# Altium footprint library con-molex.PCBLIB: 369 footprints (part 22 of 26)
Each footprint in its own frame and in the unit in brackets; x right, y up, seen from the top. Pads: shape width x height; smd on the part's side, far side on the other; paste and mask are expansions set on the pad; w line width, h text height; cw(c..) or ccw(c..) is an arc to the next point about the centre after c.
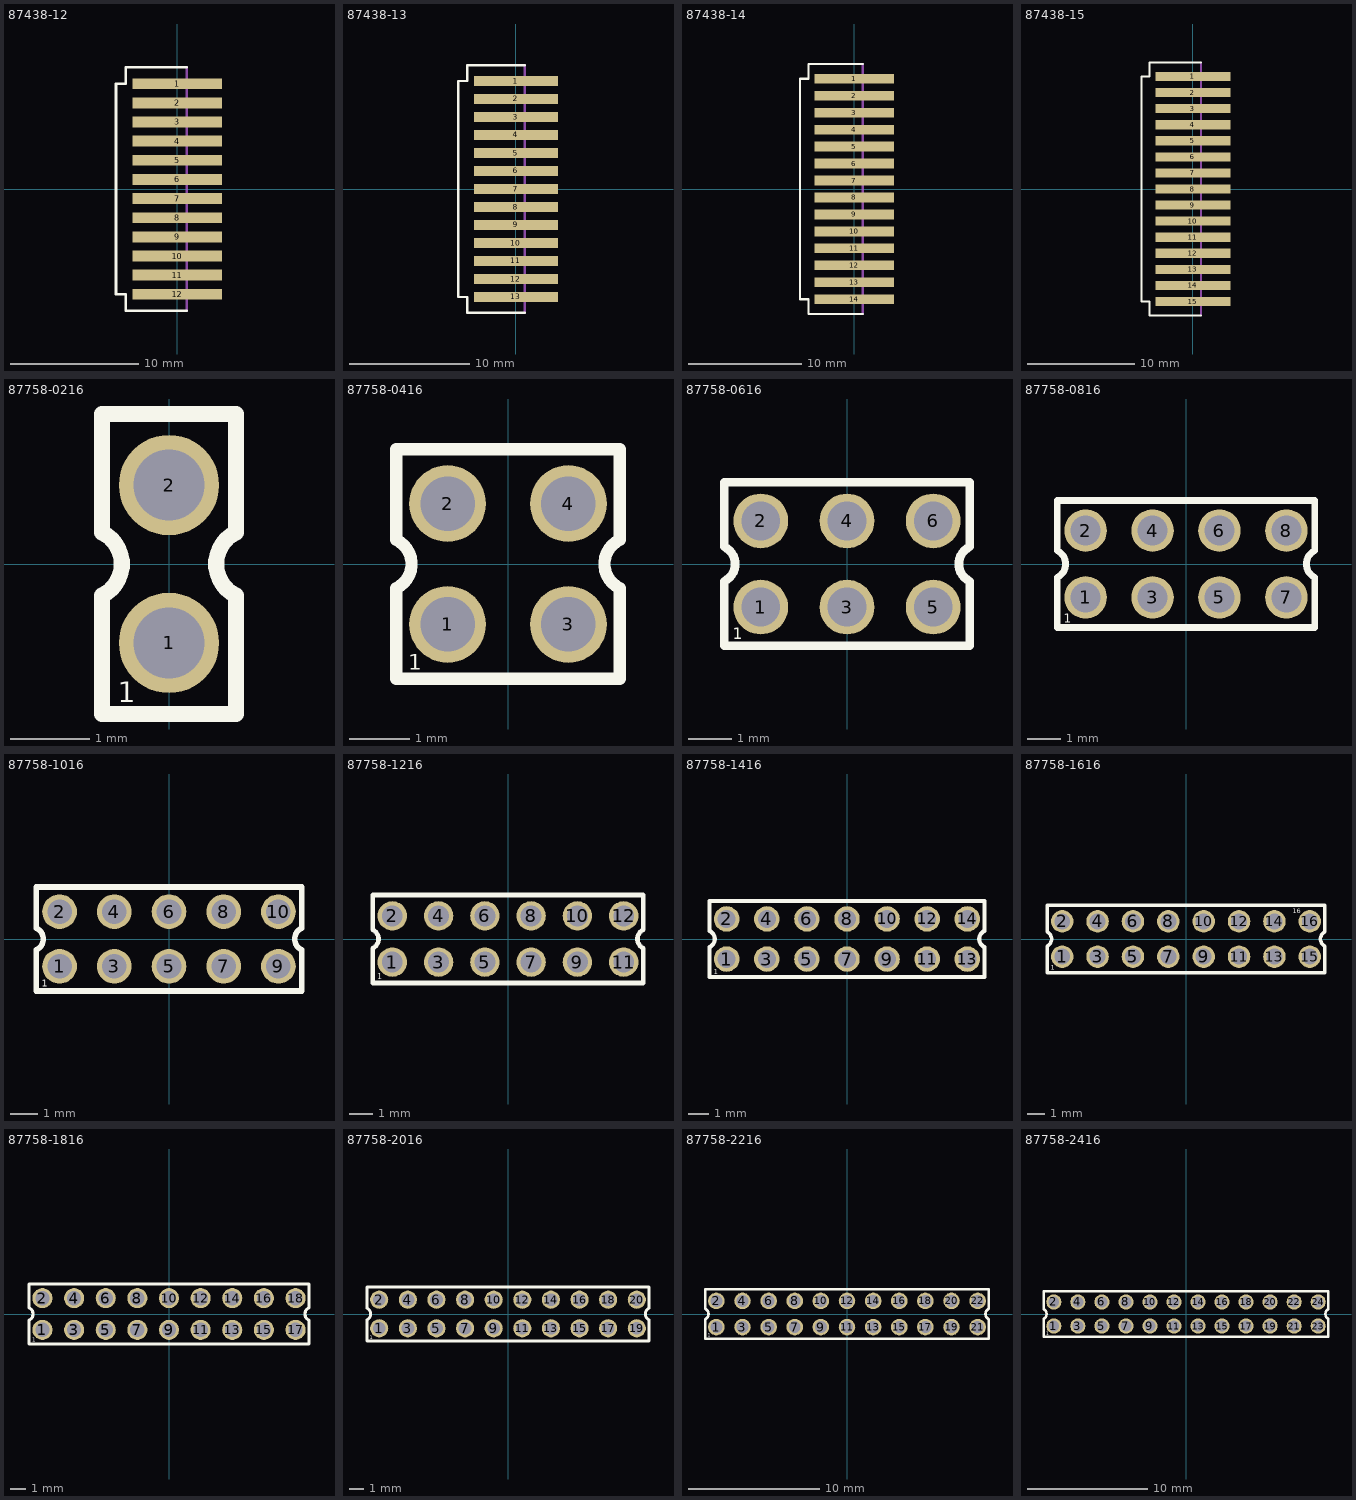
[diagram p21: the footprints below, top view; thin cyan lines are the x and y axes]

## 87438-12 [mm]
pads (12):
  rect 7x0.85 smd: 1(0,8.25) 2(0,6.75) 3(0,5.25) 4(0,3.75) 5(0,2.25) 6(0,0.75) 7(0,-0.75) 8(0,-2.25) 9(0,-3.75) 10(0,-5.25) 11(0,-6.75) 12(0,-8.25)
Top Overlay:
  lines w0.203: 0.75,-9.55 -4.05,-9.55 -4.05,-8.25 -4.8,-8.25 -4.8,8.25 -4.05,8.25 -4.05,9.55 0.75,9.55
Mechanical 16:
  rectangle: 0.8,8.025 2.85,8.475
  rectangle: 0.8,6.525 2.85,6.975
  rectangle: 0.8,5.025 2.85,5.475
  rectangle: 0.8,3.525 2.85,3.975
  rectangle: 0.8,2.025 2.85,2.475
  rectangle: 0.8,0.525 2.85,0.975
  rectangle: 0.8,-0.975 2.85,-0.525
  rectangle: 0.8,-2.475 2.85,-2.025
  rectangle: 0.8,-3.975 2.85,-3.525
  rectangle: 0.8,-5.475 2.85,-5.025
  rectangle: 0.8,-6.975 2.85,-6.525
  rectangle: 0.8,-8.475 2.85,-8.025
  lines w0.203: 0.75,-9.55 0.75,9.55

## 87438-13 [mm]
pads (13):
  rect 7x0.85 smd: 1(0,9) 2(0,7.5) 3(0,6) 4(0,4.5) 5(0,3) 6(0,1.5) 7(0,0) 8(0,-1.5) 9(0,-3) 10(0,-4.5) 11(0,-6) 12(0,-7.5) 13(0,-9)
Top Overlay:
  lines w0.203: 0.75,-10.3 -4.05,-10.3 -4.05,-9 -4.8,-9 -4.8,9 -4.05,9 -4.05,10.3 0.75,10.3
Mechanical 16:
  rectangle: 0.8,8.775 2.85,9.225
  rectangle: 0.8,7.275 2.85,7.725
  rectangle: 0.8,5.775 2.85,6.225
  rectangle: 0.8,4.275 2.85,4.725
  rectangle: 0.8,2.775 2.85,3.225
  rectangle: 0.8,1.275 2.85,1.725
  rectangle: 0.8,-0.225 2.85,0.225
  rectangle: 0.8,-1.725 2.85,-1.275
  rectangle: 0.8,-3.225 2.85,-2.775
  rectangle: 0.8,-4.725 2.85,-4.275
  rectangle: 0.8,-6.225 2.85,-5.775
  rectangle: 0.8,-7.725 2.85,-7.275
  rectangle: 0.8,-9.225 2.85,-8.775
  lines w0.203: 0.75,-10.3 0.75,10.3

## 87438-14 [mm]
pads (14):
  rect 7x0.85 smd: 1(0,9.75) 2(0,8.25) 3(0,6.75) 4(0,5.25) 5(0,3.75) 6(0,2.25) 7(0,0.75) 8(0,-0.75) 9(0,-2.25) 10(0,-3.75) 11(0,-5.25) 12(0,-6.75) 13(0,-8.25) 14(0,-9.75)
Top Overlay:
  lines w0.203: 0.75,-11.05 -4.05,-11.05 -4.05,-9.75 -4.8,-9.75 -4.8,9.75 -4.05,9.75 -4.05,11.05 0.75,11.05
Mechanical 16:
  rectangle: 0.8,9.525 2.85,9.975
  rectangle: 0.8,8.025 2.85,8.475
  rectangle: 0.8,6.525 2.85,6.975
  rectangle: 0.8,5.025 2.85,5.475
  rectangle: 0.8,3.525 2.85,3.975
  rectangle: 0.8,2.025 2.85,2.475
  rectangle: 0.8,0.525 2.85,0.975
  rectangle: 0.8,-0.975 2.85,-0.525
  rectangle: 0.8,-2.475 2.85,-2.025
  rectangle: 0.8,-3.975 2.85,-3.525
  rectangle: 0.8,-5.475 2.85,-5.025
  rectangle: 0.8,-6.975 2.85,-6.525
  rectangle: 0.8,-8.475 2.85,-8.025
  rectangle: 0.8,-9.975 2.85,-9.525
  lines w0.203: 0.75,-11.05 0.75,11.05

## 87438-15 [mm]
pads (15):
  rect 7x0.85 smd: 1(0,10.5) 2(0,9) 3(0,7.5) 4(0,6) 5(0,4.5) 6(0,3) 7(0,1.5) 8(0,0) 9(0,-1.5) 10(0,-3) 11(0,-4.5) 12(0,-6) 13(0,-7.5) 14(0,-9) 15(0,-10.5)
Top Overlay:
  lines w0.203: 0.75,-11.8 -4.05,-11.8 -4.05,-10.5 -4.8,-10.5 -4.8,10.5 -4.05,10.5 -4.05,11.8 0.75,11.8
Mechanical 16:
  rectangle: 0.8,10.275 2.85,10.725
  rectangle: 0.8,8.775 2.85,9.225
  rectangle: 0.8,7.275 2.85,7.725
  rectangle: 0.8,5.775 2.85,6.225
  rectangle: 0.8,4.275 2.85,4.725
  rectangle: 0.8,2.775 2.85,3.225
  rectangle: 0.8,1.275 2.85,1.725
  rectangle: 0.8,-0.225 2.85,0.225
  rectangle: 0.8,-1.725 2.85,-1.275
  rectangle: 0.8,-3.225 2.85,-2.775
  rectangle: 0.8,-4.725 2.85,-4.275
  rectangle: 0.8,-6.225 2.85,-5.775
  rectangle: 0.8,-7.725 2.85,-7.275
  rectangle: 0.8,-9.225 2.85,-8.775
  rectangle: 0.8,-10.725 2.85,-10.275
  lines w0.203: 0.75,-11.8 0.75,11.8

## 87758-0216 [mm]
pads (2):
  round 1.27 hole 0.9: 1(0,-1) 2(0,1)
Top Overlay:
  lines w0.203: -0.85,-1.9 0.85,-1.9 0.85,-0.4 cw(c1.04,0) 0.85,0.4 0.85,1.9 -0.85,1.9 -0.85,0.4 cw(c-1.04,0) -0.85,-0.4 -0.85,-1.9
  text "1" at -0.65,-1.75 h0.26
Mechanical 16:
  rectangle: -0.25,-1.25 0.25,-0.75
  rectangle: -0.25,0.75 0.25,1.25

## 87758-0416 [mm]
pads (4):
  round 1.27 hole 0.9: 1(-1,-1) 2(-1,1) 3(1,-1) 4(1,1)
Top Overlay:
  lines w0.203: -1.85,-1.9 1.85,-1.9 1.85,-0.4 cw(c2.04,0) 1.85,0.4 1.85,1.9 -1.85,1.9 -1.85,0.4 cw(c-2.04,0) -1.85,-0.4 -1.85,-1.9
  text "1" at -1.65,-1.75 h0.26
Mechanical 16:
  rectangle: -1.25,-1.25 -0.75,-0.75
  rectangle: -1.25,0.75 -0.75,1.25
  rectangle: 0.75,-1.25 1.25,-0.75
  rectangle: 0.75,0.75 1.25,1.25

## 87758-0616 [mm]
pads (6):
  round 1.27 hole 0.9: 1(-2,-1) 2(-2,1) 3(0,-1) 4(0,1) 5(2,-1) 6(2,1)
Top Overlay:
  lines w0.203: -2.85,-1.9 2.85,-1.9 2.85,-0.4 cw(c3.04,0) 2.85,0.4 2.85,1.9 -2.85,1.9 -2.85,0.4 cw(c-3.04,0) -2.85,-0.4 -2.85,-1.9
  text "1" at -2.65,-1.75 h0.26
Mechanical 16:
  rectangle: -2.25,-1.25 -1.75,-0.75
  rectangle: -2.25,0.75 -1.75,1.25
  rectangle: -0.25,-1.25 0.25,-0.75
  rectangle: -0.25,0.75 0.25,1.25
  rectangle: 1.75,-1.25 2.25,-0.75
  rectangle: 1.75,0.75 2.25,1.25

## 87758-0816 [mm]
pads (8):
  round 1.27 hole 0.9: 1(-3,-1) 2(-3,1) 3(-1,-1) 4(-1,1) 5(1,-1) 6(1,1) 7(3,-1) 8(3,1)
Top Overlay:
  lines w0.203: -3.85,-1.9 3.85,-1.9 3.85,-0.4 cw(c4.04,0) 3.85,0.4 3.85,1.9 -3.85,1.9 -3.85,0.4 cw(c-4.04,0) -3.85,-0.4 -3.85,-1.9
  text "1" at -3.65,-1.75 h0.26
Mechanical 16:
  rectangle: -3.25,-1.25 -2.75,-0.75
  rectangle: -3.25,0.75 -2.75,1.25
  rectangle: -1.25,-1.25 -0.75,-0.75
  rectangle: -1.25,0.75 -0.75,1.25
  rectangle: 0.75,-1.25 1.25,-0.75
  rectangle: 0.75,0.75 1.25,1.25
  rectangle: 2.75,-1.25 3.25,-0.75
  rectangle: 2.75,0.75 3.25,1.25

## 87758-1016 [mm]
pads (10):
  round 1.27 hole 0.9: 1(-4,-1) 2(-4,1) 3(-2,-1) 4(-2,1) 5(0,-1) 6(0,1) 7(2,-1) 8(2,1) 9(4,-1) 10(4,1)
Top Overlay:
  lines w0.203: -4.85,-1.9 4.85,-1.9 4.85,-0.4 cw(c5.04,0) 4.85,0.4 4.85,1.9 -4.85,1.9 -4.85,0.4 cw(c-5.04,0) -4.85,-0.4 -4.85,-1.9
  text "1" at -4.65,-1.75 h0.26
Mechanical 16:
  rectangle: -4.25,-1.25 -3.75,-0.75
  rectangle: -4.25,0.75 -3.75,1.25
  rectangle: -2.25,-1.25 -1.75,-0.75
  rectangle: -2.25,0.75 -1.75,1.25
  rectangle: -0.25,-1.25 0.25,-0.75
  rectangle: -0.25,0.75 0.25,1.25
  rectangle: 1.75,-1.25 2.25,-0.75
  rectangle: 1.75,0.75 2.25,1.25
  rectangle: 3.75,-1.25 4.25,-0.75
  rectangle: 3.75,0.75 4.25,1.25

## 87758-1216 [mm]
pads (12):
  round 1.27 hole 0.9: 1(-5,-1) 2(-5,1) 3(-3,-1) 4(-3,1) 5(-1,-1) 6(-1,1) 7(1,-1) 8(1,1) 9(3,-1) 10(3,1) 11(5,-1) 12(5,1)
Top Overlay:
  lines w0.203: -5.85,-1.9 5.85,-1.9 5.85,-0.4 cw(c6.04,0) 5.85,0.4 5.85,1.9 -5.85,1.9 -5.85,0.4 cw(c-6.04,0) -5.85,-0.4 -5.85,-1.9
  text "1" at -5.65,-1.75 h0.26
Mechanical 16:
  rectangle: -5.25,-1.25 -4.75,-0.75
  rectangle: -5.25,0.75 -4.75,1.25
  rectangle: -3.25,-1.25 -2.75,-0.75
  rectangle: -3.25,0.75 -2.75,1.25
  rectangle: -1.25,-1.25 -0.75,-0.75
  rectangle: -1.25,0.75 -0.75,1.25
  rectangle: 0.75,-1.25 1.25,-0.75
  rectangle: 0.75,0.75 1.25,1.25
  rectangle: 2.75,-1.25 3.25,-0.75
  rectangle: 2.75,0.75 3.25,1.25
  rectangle: 4.75,-1.25 5.25,-0.75
  rectangle: 4.75,0.75 5.25,1.25

## 87758-1416 [mm]
pads (14):
  round 1.27 hole 0.9: 1(-6,-1) 2(-6,1) 3(-4,-1) 4(-4,1) 5(-2,-1) 6(-2,1) 7(0,-1) 8(0,1) 9(2,-1) 10(2,1) 11(4,-1) 12(4,1) 13(6,-1) 14(6,1)
Top Overlay:
  lines w0.203: -6.85,-1.9 6.85,-1.9 6.85,-0.4 cw(c7.04,0) 6.85,0.4 6.85,1.9 -6.85,1.9 -6.85,0.4 cw(c-7.04,0) -6.85,-0.4 -6.85,-1.9
  text "1" at -6.65,-1.75 h0.26
Mechanical 16:
  rectangle: -6.25,-1.25 -5.75,-0.75
  rectangle: -6.25,0.75 -5.75,1.25
  rectangle: -4.25,-1.25 -3.75,-0.75
  rectangle: -4.25,0.75 -3.75,1.25
  rectangle: -2.25,-1.25 -1.75,-0.75
  rectangle: -2.25,0.75 -1.75,1.25
  rectangle: -0.25,-1.25 0.25,-0.75
  rectangle: -0.25,0.75 0.25,1.25
  rectangle: 1.75,-1.25 2.25,-0.75
  rectangle: 1.75,0.75 2.25,1.25
  rectangle: 3.75,-1.25 4.25,-0.75
  rectangle: 3.75,0.75 4.25,1.25
  rectangle: 5.75,-1.25 6.25,-0.75
  rectangle: 5.75,0.75 6.25,1.25

## 87758-1616 [mm]
pads (16):
  round 1.27 hole 0.9: 1(-7,-1) 2(-7,1) 3(-5,-1) 4(-5,1) 5(-3,-1) 6(-3,1) 7(-1,-1) 8(-1,1) 9(1,-1) 10(1,1) 11(3,-1) 12(3,1) 13(5,-1) 14(5,1) 15(7,-1) 16(7,1)
Top Overlay:
  lines w0.203: -7.85,-1.9 7.85,-1.9 7.85,-0.4 cw(c8.04,0) 7.85,0.4 7.85,1.9 -7.85,1.9 -7.85,0.4 cw(c-8.04,0) -7.85,-0.4 -7.85,-1.9
  text "1" at -7.65,-1.75 h0.26
  text "16" at 6.025,1.45 h0.26
Mechanical 16:
  rectangle: -7.25,-1.25 -6.75,-0.75
  rectangle: -7.25,0.75 -6.75,1.25
  rectangle: -5.25,-1.25 -4.75,-0.75
  rectangle: -5.25,0.75 -4.75,1.25
  rectangle: -3.25,-1.25 -2.75,-0.75
  rectangle: -3.25,0.75 -2.75,1.25
  rectangle: -1.25,-1.25 -0.75,-0.75
  rectangle: -1.25,0.75 -0.75,1.25
  rectangle: 0.75,-1.25 1.25,-0.75
  rectangle: 0.75,0.75 1.25,1.25
  rectangle: 2.75,-1.25 3.25,-0.75
  rectangle: 2.75,0.75 3.25,1.25
  rectangle: 4.75,-1.25 5.25,-0.75
  rectangle: 4.75,0.75 5.25,1.25
  rectangle: 6.75,-1.25 7.25,-0.75
  rectangle: 6.75,0.75 7.25,1.25

## 87758-1816 [mm]
pads (18):
  round 1.27 hole 0.9: 1(-8,-1) 2(-8,1) 3(-6,-1) 4(-6,1) 5(-4,-1) 6(-4,1) 7(-2,-1) 8(-2,1) 9(0,-1) 10(0,1) 11(2,-1) 12(2,1) 13(4,-1) 14(4,1) 15(6,-1) 16(6,1) 17(8,-1) 18(8,1)
Top Overlay:
  lines w0.203: -8.85,-1.9 8.85,-1.9 8.85,-0.4 cw(c9.04,0) 8.85,0.4 8.85,1.9 -8.85,1.9 -8.85,0.4 cw(c-9.04,0) -8.85,-0.4 -8.85,-1.9
  text "1" at -8.65,-1.75 h0.26
Mechanical 16:
  rectangle: -8.25,-1.25 -7.75,-0.75
  rectangle: -8.25,0.75 -7.75,1.25
  rectangle: -6.25,-1.25 -5.75,-0.75
  rectangle: -6.25,0.75 -5.75,1.25
  rectangle: -4.25,-1.25 -3.75,-0.75
  rectangle: -4.25,0.75 -3.75,1.25
  rectangle: -2.25,-1.25 -1.75,-0.75
  rectangle: -2.25,0.75 -1.75,1.25
  rectangle: -0.25,-1.25 0.25,-0.75
  rectangle: -0.25,0.75 0.25,1.25
  rectangle: 1.75,-1.25 2.25,-0.75
  rectangle: 1.75,0.75 2.25,1.25
  rectangle: 3.75,-1.25 4.25,-0.75
  rectangle: 3.75,0.75 4.25,1.25
  rectangle: 5.75,-1.25 6.25,-0.75
  rectangle: 5.75,0.75 6.25,1.25
  rectangle: 7.75,-1.25 8.25,-0.75
  rectangle: 7.75,0.75 8.25,1.25

## 87758-2016 [mm]
pads (20):
  round 1.27 hole 0.9: 1(-9,-1) 2(-9,1) 3(-7,-1) 4(-7,1) 5(-5,-1) 6(-5,1) 7(-3,-1) 8(-3,1) 9(-1,-1) 10(-1,1) 11(1,-1) 12(1,1) 13(3,-1) 14(3,1) 15(5,-1) 16(5,1) 17(7,-1) 18(7,1) 19(9,-1) 20(9,1)
Top Overlay:
  lines w0.203: -9.85,-1.9 9.85,-1.9 9.85,-0.4 cw(c10.04,0) 9.85,0.4 9.85,1.9 -9.85,1.9 -9.85,0.4 cw(c-10.04,0) -9.85,-0.4 -9.85,-1.9
  text "1" at -9.65,-1.75 h0.26
Mechanical 16:
  rectangle: -9.25,-1.25 -8.75,-0.75
  rectangle: -9.25,0.75 -8.75,1.25
  rectangle: -7.25,-1.25 -6.75,-0.75
  rectangle: -7.25,0.75 -6.75,1.25
  rectangle: -5.25,-1.25 -4.75,-0.75
  rectangle: -5.25,0.75 -4.75,1.25
  rectangle: -3.25,-1.25 -2.75,-0.75
  rectangle: -3.25,0.75 -2.75,1.25
  rectangle: -1.25,-1.25 -0.75,-0.75
  rectangle: -1.25,0.75 -0.75,1.25
  rectangle: 0.75,-1.25 1.25,-0.75
  rectangle: 0.75,0.75 1.25,1.25
  rectangle: 2.75,-1.25 3.25,-0.75
  rectangle: 2.75,0.75 3.25,1.25
  rectangle: 4.75,-1.25 5.25,-0.75
  rectangle: 4.75,0.75 5.25,1.25
  rectangle: 6.75,-1.25 7.25,-0.75
  rectangle: 6.75,0.75 7.25,1.25
  rectangle: 8.75,-1.25 9.25,-0.75
  rectangle: 8.75,0.75 9.25,1.25

## 87758-2216 [mm]
pads (22):
  round 1.27 hole 0.9: 1(-10,-1) 2(-10,1) 3(-8,-1) 4(-8,1) 5(-6,-1) 6(-6,1) 7(-4,-1) 8(-4,1) 9(-2,-1) 10(-2,1) 11(0,-1) 12(0,1) 13(2,-1) 14(2,1) 15(4,-1) 16(4,1) 17(6,-1) 18(6,1) 19(8,-1) 20(8,1) 21(10,-1) 22(10,1)
Top Overlay:
  lines w0.203: -10.85,-1.9 10.85,-1.9 10.85,-0.4 cw(c11.04,0) 10.85,0.4 10.85,1.9 -10.85,1.9 -10.85,0.4 cw(c-11.04,0) -10.85,-0.4 -10.85,-1.9
  text "1" at -10.65,-1.75 h0.26
Mechanical 16:
  rectangle: -10.25,-1.25 -9.75,-0.75
  rectangle: -10.25,0.75 -9.75,1.25
  rectangle: -8.25,-1.25 -7.75,-0.75
  rectangle: -8.25,0.75 -7.75,1.25
  rectangle: -6.25,-1.25 -5.75,-0.75
  rectangle: -6.25,0.75 -5.75,1.25
  rectangle: -4.25,-1.25 -3.75,-0.75
  rectangle: -4.25,0.75 -3.75,1.25
  rectangle: -2.25,-1.25 -1.75,-0.75
  rectangle: -2.25,0.75 -1.75,1.25
  rectangle: -0.25,-1.25 0.25,-0.75
  rectangle: -0.25,0.75 0.25,1.25
  rectangle: 1.75,-1.25 2.25,-0.75
  rectangle: 1.75,0.75 2.25,1.25
  rectangle: 3.75,-1.25 4.25,-0.75
  rectangle: 3.75,0.75 4.25,1.25
  rectangle: 5.75,-1.25 6.25,-0.75
  rectangle: 5.75,0.75 6.25,1.25
  rectangle: 7.75,-1.25 8.25,-0.75
  rectangle: 7.75,0.75 8.25,1.25
  rectangle: 9.75,-1.25 10.25,-0.75
  rectangle: 9.75,0.75 10.25,1.25

## 87758-2416 [mm]
pads (24):
  round 1.27 hole 0.9: 1(-11,-1) 2(-11,1) 3(-9,-1) 4(-9,1) 5(-7,-1) 6(-7,1) 7(-5,-1) 8(-5,1) 9(-3,-1) 10(-3,1) 11(-1,-1) 12(-1,1) 13(1,-1) 14(1,1) 15(3,-1) 16(3,1) 17(5,-1) 18(5,1) 19(7,-1) 20(7,1) 21(9,-1) 22(9,1) 23(11,-1) 24(11,1)
Top Overlay:
  lines w0.203: -11.85,-1.9 11.85,-1.9 11.85,-0.4 cw(c12.04,0) 11.85,0.4 11.85,1.9 -11.85,1.9 -11.85,0.4 cw(c-12.04,0) -11.85,-0.4 -11.85,-1.9
  text "1" at -11.65,-1.75 h0.26
Mechanical 16:
  rectangle: -11.25,-1.25 -10.75,-0.75
  rectangle: -11.25,0.75 -10.75,1.25
  rectangle: -9.25,-1.25 -8.75,-0.75
  rectangle: -9.25,0.75 -8.75,1.25
  rectangle: -7.25,-1.25 -6.75,-0.75
  rectangle: -7.25,0.75 -6.75,1.25
  rectangle: -5.25,-1.25 -4.75,-0.75
  rectangle: -5.25,0.75 -4.75,1.25
  rectangle: -3.25,-1.25 -2.75,-0.75
  rectangle: -3.25,0.75 -2.75,1.25
  rectangle: -1.25,-1.25 -0.75,-0.75
  rectangle: -1.25,0.75 -0.75,1.25
  rectangle: 0.75,-1.25 1.25,-0.75
  rectangle: 0.75,0.75 1.25,1.25
  rectangle: 2.75,-1.25 3.25,-0.75
  rectangle: 2.75,0.75 3.25,1.25
  rectangle: 4.75,-1.25 5.25,-0.75
  rectangle: 4.75,0.75 5.25,1.25
  rectangle: 6.75,-1.25 7.25,-0.75
  rectangle: 6.75,0.75 7.25,1.25
  rectangle: 8.75,-1.25 9.25,-0.75
  rectangle: 8.75,0.75 9.25,1.25
  rectangle: 10.75,-1.25 11.25,-0.75
  rectangle: 10.75,0.75 11.25,1.25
